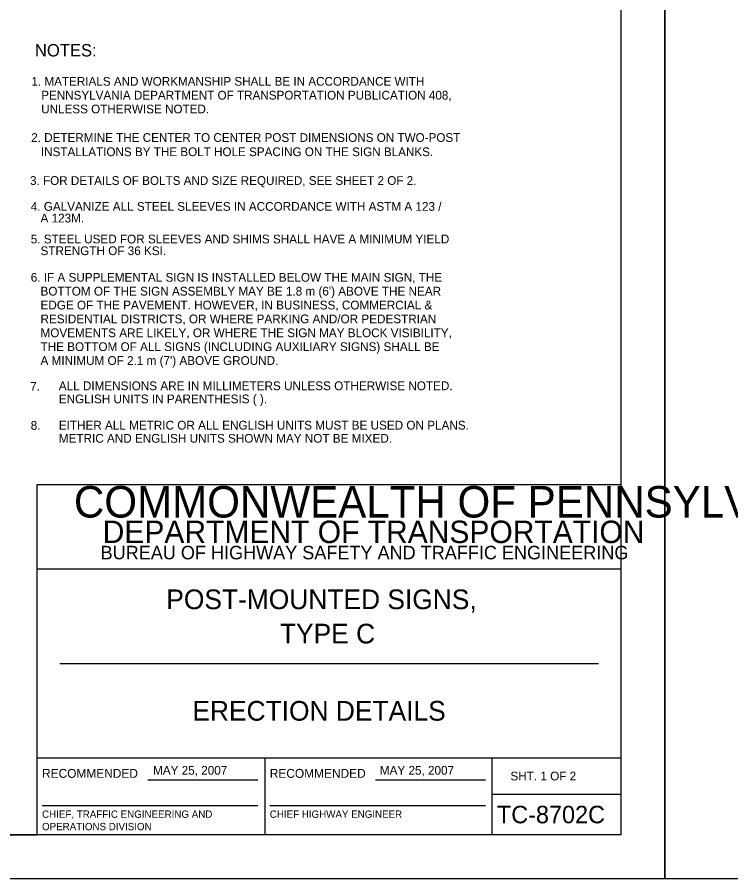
# Model space of a CAD drawing. Extents: x 649454 to 651200, y 295188 to 295782.
# Drawn here: x 650073.5 to 650317.9, y 295187.6 to 295482.7 of the extents above; entities that cross this region are included whole.
import ezdxf

# ---------------------------------------------------------------- set-up
doc = ezdxf.new("R2010")
doc.units = 0
for name, color, linetype in [('1', 7, 'Continuous'), ('2', 7, 'Continuous'), ('3', 7, 'Continuous'), ('PLT-BNDY', 7, 'Continuous')]:
    doc.layers.add(name, color=color, linetype=linetype)

msp = doc.modelspace()

# ---------------------------------------------------------------- linework, layer by layer
at = {"layer": '1'}
for p, q in [((650280.31, 295202.63), (650280.31, 295766.63)), ((650080.31, 295202.63), (650080.31, 295322.63)), ((650080.31, 295322.63), (650280.31, 295322.63)), ((650280.31, 295293.63), (650080.31, 295293.63)), ((650088.06, 295261.31), (650272.56, 295261.31)), ((650080.31, 295229), (650280.31, 295229)), ((650158.31, 295229), (650158.31, 295202.63)), ((650236.19, 295202.63), (650236.19, 295229)), ((650118.24, 295221.57), (650155.87, 295221.57)), ((650196.24, 295221.57), (650233.87, 295221.57)), ((650236.19, 295216.63), (650280.31, 295216.63)), ((650081.99, 295212.68), (650155.87, 295212.68)), ((650159.99, 295212.68), (650233.87, 295212.68)), ((650280.31, 295202.63), (649494.31, 295202.63)), ((649494.31, 295202.63), (650080.31, 295202.63))]:
    msp.add_line(p, q, dxfattribs=at)
at = {"layer": 'PLT-BNDY'}
for points in [[(649454.31, 295781.63), (650295.31, 295781.63), (650295.31, 295187.63), (649454.31, 295187.63)], [(650295.31, 295781.63), (651136.31, 295781.63), (651136.31, 295187.63), (650295.31, 295187.63)]]:
    msp.add_lwpolyline(points, close=True, dxfattribs=at)

# ---------------------------------------------------------------- texts
at = {"layer": '1'}
for s, height, p in [('COMMONWEALTH OF PENNSYLVANIA', 10.7828, (650092.9, 295311.36)), ('DEPARTMENT OF TRANSPORTATION', 7.6837, (650102.76, 295302.61)), ('BUREAU OF HIGHWAY SAFETY AND TRAFFIC ENGINEERING', 4.6253, (650102.04, 295297.04)), ('POST-MOUNTED SIGNS,', 6.75, (650124.54, 295279.97)), ('TYPE C', 6.75, (650163.45, 295268.22)), ('ERECTION DETAILS', 6.75, (650133.47, 295241.78)), ('RECOMMENDED', 3.048, (650081.99, 295222.2)), ('RECOMMENDED', 3.048, (650159.99, 295222.2)), ('SHT. 1 OF 2', 3, (650242.4, 295221.31)), ('TC-8702C', 6, (650237.77, 295206.63)), ('CHIEF, TRAFFIC ENGINEERING AND', 2.5, (650081.99, 295208.51)), ('CHIEF HIGHWAY ENGINEER', 2.5, (650159.99, 295208.51)), ('OPERATIONS DIVISION', 2.5, (650081.99, 295204.26))]:
    msp.add_text(s, height=height, dxfattribs=at).set_placement(p)
at = {"layer": '2'}
for p in [(650120, 295223.27), (650197.67, 295223.27)]:
    msp.add_text('MAY 25, 2007', height=3, dxfattribs=at).set_placement(p)
at = {"layer": '3'}
for s, height, p in [('NOTES:', 4.25, (650079.54, 295469.28)), ('1. MATERIALS AND WORKMANSHIP SHALL BE IN ACCORDANCE WITH ', 2.988, (650078.37, 295459.26)), ('   PENNSYLVANIA DEPARTMENT OF TRANSPORTATION PUBLICATION 408,', 2.988, (650078.37, 295454.52)), ('   UNLESS OTHERWISE NOTED.', 2.988, (650078.37, 295449.79)), ('2. DETERMINE THE CENTER TO CENTER POST DIMENSIONS ON TWO-POST', 2.988, (650078.28, 295440.02)), ('   INSTALLATIONS BY THE BOLT HOLE SPACING ON THE SIGN BLANKS.', 2.988, (650078.28, 295435.14)), ('3. FOR DETAILS OF BOLTS AND SIZE REQUIRED, SEE SHEET 2 OF 2.', 2.988, (650077.87, 295425.29)), ('4. GALVANIZE ALL STEEL SLEEVES IN ACCORDANCE WITH ASTM A 123 /', 3, (650078.12, 295416.42)), ('   A 123M.', 3, (650078.12, 295412.42)), ('5. STEEL USED FOR SLEEVES AND SHIMS SHALL HAVE A MINIMUM YIELD', 3, (650078.12, 295405.25)), ('   STRENGTH OF 36 KSI.', 3, (650078.12, 295401.24)), ('6. IF A SUPPLEMENTAL SIGN IS INSTALLED BELOW THE MAIN SIGN, THE', 3, (650078.12, 295392.13)), ("   BOTTOM OF THE SIGN ASSEMBLY MAY BE 1.8 m (6') ABOVE THE NEAR", 3, (650078.12, 295387.38)), ('   EDGE OF THE PAVEMENT. HOWEVER, IN BUSINESS, COMMERCIAL & ', 3, (650078.12, 295382.63)), ('   RESIDENTIAL DISTRICTS, OR WHERE PARKING AND/OR PEDESTRIAN', 3, (650078.12, 295377.88)), ('   MOVEMENTS ARE LIKELY, OR WHERE THE SIGN MAY BLOCK VISIBILITY,', 3, (650078.12, 295373.13)), ('   THE BOTTOM OF ALL SIGNS (INCLUDING AUXILIARY SIGNS) SHALL BE', 3, (650078.12, 295368.38)), ("   A MINIMUM OF 2.1 m (7') ABOVE GROUND.", 3, (650078.12, 295363.63)), ('7.', 3, (650077.91, 295354.77)), ('ALL DIMENSIONS ARE IN MILLIMETERS UNLESS OTHERWISE NOTED.  ', 3, (650087.73, 295354.98)), ('ENGLISH UNITS IN PARENTHESIS ( ).', 3, (650087.73, 295350.48)), ('8.', 3, (650078.1, 295341.41)), ('EITHER ALL METRIC OR ALL ENGLISH UNITS MUST BE USED ON PLANS.  ', 3, (650087.73, 295341.48)), ('METRIC AND ENGLISH UNITS SHOWN MAY NOT BE MIXED.', 3, (650087.73, 295336.98))]:
    msp.add_text(s, height=height, dxfattribs=at).set_placement(p)

doc.saveas('drawing.dxf')
